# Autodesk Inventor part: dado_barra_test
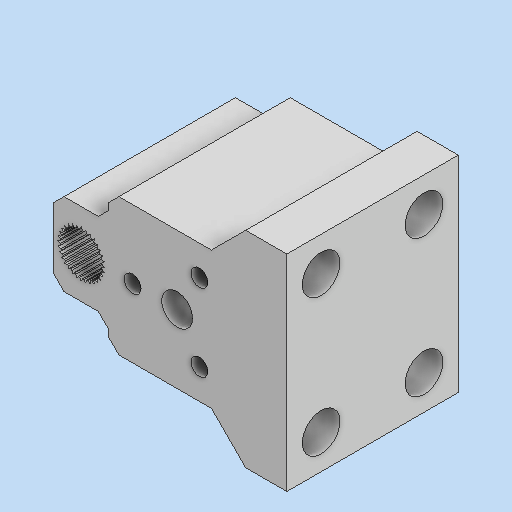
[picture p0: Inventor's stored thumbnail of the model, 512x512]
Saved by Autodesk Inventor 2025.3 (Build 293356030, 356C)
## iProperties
Created: 2025-12
Part Number: dado_barra_test
Material: Generico
Document SubType Name: Modeling
Designer: Ryzen5700u
Density: 1 g/cm^3
Appearance: Default
Author: Ryzen5700u
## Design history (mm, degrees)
sketch "Schizzo1"
  geometry: L1 (-10, 10)-(10, 10); L2 (10, 10)-(10, -10); L3 (10, -10)-(-10, -10); L4 (-10, -10)-(-10, 10); L5 (-10, 10)-(10, -10); L6 (10, 10)-(-10, -10); L7 (-10, 6)-(-18, 6); L8 (-18, 6)-(-18, -6); L9 (-18, -6)-(-10, -6); L10 (-10, -6)-(-10, 6); L11 (0, 0)-(-22.766, 0); C1 r 1.621 at (-14, 0) reference; C2 r 3.05 at (-14, 0); C3 r 1.23 at (3.25, 5.629) reference; C4 r 1.23 at (3.25, -5.629) reference; C5 r 1.23 at (-6.5, 0) reference; C6 r 2.25 at (0, 0); 1 further point
  constraints: 22 end point, 4 parallel, 3 horizontal, 2 centre point, 2 coincident, 2 midpoint, 2 perpendicular, 1 point on line, 1 other
  dimensions: "d0" = 20 distance of L2.end L3.end; "d1" = 20 distance of L1.end L2.end; "d2" = 8 distance of L9.end L8.end; "d3" = 12 distance of L8.end L7.end; "d4" = 6.1 diameter of C2; "d7" = 4.5 diameter of C6
extrude "Estrusione1" new body sketch "Schizzo1" distance "d5" = 25; taper "d6" = 0 deg
sketch "Schizzo2"
  geometry: L1 (-14, 0)-(-6.5, 0); L2 (-14, 0.2)-(-6.5, 0.2); L3 (-14, -0.2)-(-6.5, -0.2); L4 (-10.957, -0.2)-(-10.592, 0); L5 (-10.957, 0.2)-(-10.592, 0); C1 r 1.23 at (-6.5, 0) reference; A1 r 3.05 centre (-14, 0) between (-10.957, -0.2) and (-10.957, 0.2) reference; 1 further point
  constraints: 10 end point, 3 point on line, 2 parallel, 2 point on circle, 1 horizontal
  dimensions: "d9" = 0.2 distance between parallel lines of L1 L2; "d10" = 0.2 distance between parallel lines of L1 L3
extrude "Estrusione2" cut sketch "Schizzo2" extent not by distance; stored distance "d11" = 0; taper "d12" = 0 deg
chamfer "Smusso1" distance "d16" = 1.5; stored, may be unused: second distance "d17" = 2, angle "d18" = 45 deg
sketch "Schizzo3"
  geometry: L1 (0, 0)-(0, 20) reference; L2 (0, 20)-(-25, 20) reference; L3 (-25, 0)-(-25, 20) reference; L4 (0, 0)-(-25, 0) reference; L5 (-25, 25)-(0, 25); L6 (0, 25)-(0, -5); L7 (0, -5)-(-25, -5); L8 (-25, -5)-(-25, 25); L9 (-25, 10)-(0, 10) reference; L10 (-25, 25)-(0, -5); L11 (0, 25)-(-25, -5); 5 further points
  constraints: 12 end point, 3 midpoint, 2 parallel, 1 horizontal, 1 perpendicular
  dimensions: "d30" = 30 distance of L5.end L6.end
extrude "Estrusione3" join sketch "Schizzo3" distance "d19" = 6; taper "d20" = 0 deg
sketch "Schizzo4"
  geometry: L1 (-25, 20)-(0, 20) reference; L2 (-25, 0)-(-25, 1.5) reference; L3 (0, 20)-(-25, 0); L4 (0, 0)-(-25, 0) reference; L5 (-25, 0)-(0, 0); L6 (0, 0)-(-25, 20); L7 (-20, 20)-(-5, 20); L8 (-5, 20)-(-5, 0); L9 (-5, 0)-(-20, 0); L10 (-20, 0)-(-20, 20); L11 (-20, 20)-(-5, 0); L12 (-5, 20)-(-20, 0); 2 further points
  constraints: 18 end point, 3 equal length, 3 midpoint, 1 horizontal, 1 perpendicular
  dimensions: "d21" = 15 distance of L8.end L9.end; "d22" = 20 distance of L7.end L8.end
hole "Foro1" sketch "Schizzo4" at (-5, 0), (-5, 20), (-20, 0), (-20, 20) diameter "d23" = 5.5; stored, may be unused: countersink angle "d27" = 90 deg, drill point angle "d29" = 0 deg; dims "d24" = 6, "d25" = 4, "d26" = 2, "d28" = 5.5
chamfer "Smusso2" distance "d31" = 5; stored, may be unused: second distance "d32" = 2, angle "d33" = 45 deg
node "Solido1"
pattern_circular "Serie circolare1" dims angle "d14" = 360 deg
node "Riferimento1"
node "Riferimento2"
node "Riferimento3"
node "Riferimento4"
node "Linea chiusa proiettata1"
